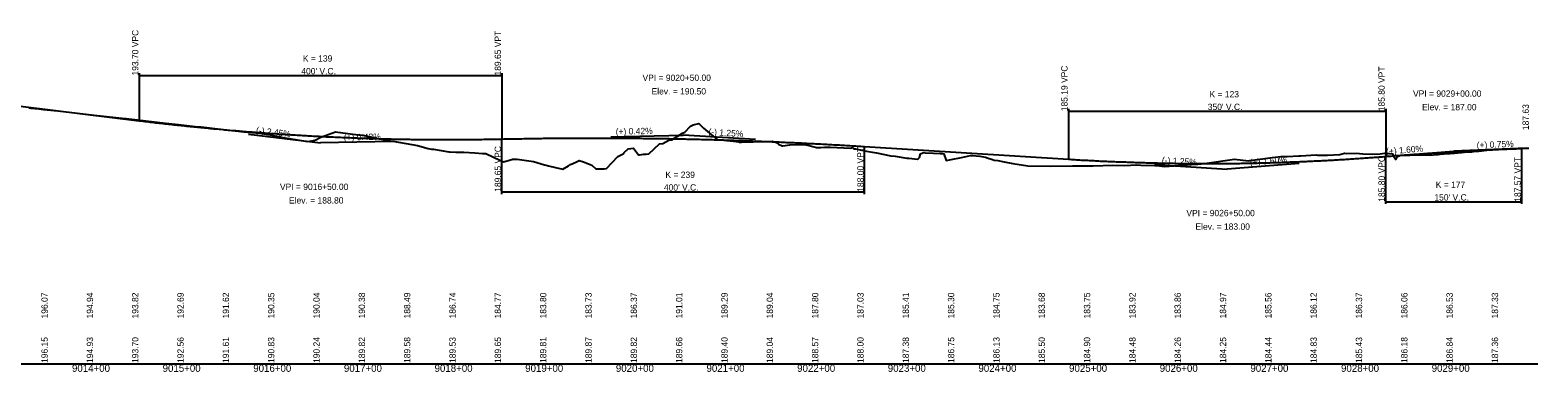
# Model space of a CAD drawing. Extents: x 1876258 to 1932803, y 754739 to 837911.
# Drawn here: x 1879018 to 1880682, y 765980 to 766358 of the extents above; entities that cross this region are included whole.
import ezdxf

# ---------------------------------------------------------------- set-up
doc = ezdxf.new("R2010")
doc.units = 0
for name, color, linetype in [('RD_DDB_GradeTX', 7, 'Continuous'), ('RD_DDB_Profile_EX', 7, 'Continuous'), ('RD_DDB_Profile_Lbl', 7, 'Continuous'), ('RD_DDB_Profile_PR', 7, 'Continuous'), ('RD_DDB_StaTX', 7, 'Continuous'), ('RD_DDB_StripGrade', 7, 'Continuous'), ('RD_DDB_VCLbl', 7, 'Continuous'), ('RD_GPK_Profile_Cell', 7, 'Continuous')]:
    doc.layers.add(name, color=color, linetype=linetype)

msp = doc.modelspace()

# ---------------------------------------------------------------- linework, layer by layer
at = {"layer": 'RD_DDB_GradeTX'}
for p, q in [((1879259.3, 766242.9), (1879338.8, 766233.1)), ((1879418.7, 766234.8), (1879338.8, 766233.1)), ((1879658.8, 766239.9), (1879738.8, 766241.6)), ((1879818.6, 766236.7), (1879738.8, 766241.6)), ((1880509, 766217.8), (1880588.8, 766224.1)), ((1880668.7, 766227.2), (1880588.8, 766224.1)), ((1880258.9, 766209.1), (1880338.8, 766204.1)), ((1880418.5, 766210.5), (1880338.8, 766204.1))]:
    msp.add_line(p, q, dxfattribs=at)
at = {"layer": 'RD_DDB_Profile_EX'}
for points in [[(1879016.8, 766271.9), (1879019.1, 766271.6), (1879027.9, 766270.7), (1879033, 766270.1), (1879049, 766268.4), (1879089.1, 766263.8), (1879123.3, 766260), (1879124.4, 766259.9), (1879167.7, 766254.9), (1879182, 766253.3), (1879182.1, 766253.3), (1879200.5, 766251.3), (1879207, 766250.7), (1879228.3, 766248.4), (1879254, 766245.5), (1879271.6, 766243.7), (1879283.3, 766242.1), (1879295.1, 766239.5), (1879324.4, 766234.8), (1879330.9, 766235.8), (1879331.3, 766235.8), (1879333.7, 766236.5), (1879339.1, 766239.5), (1879355.1, 766245.3), (1879374.2, 766242.8), (1879384.4, 766241.8), (1879385.7, 766241.7), (1879402.1, 766238.1), (1879415.4, 766235.5), (1879418.4, 766235.1), (1879439.4, 766231.5), (1879445.8, 766230.4), (1879457.6, 766227), (1879459.3, 766226.7), (1879461.1, 766226.1), (1879463.5, 766226.1), (1879480.4, 766223.2), (1879481.2, 766223.1), (1879487.9, 766222.8), (1879494.5, 766223), (1879496.9, 766222.7), (1879509, 766222.1), (1879517.4, 766221.5), (1879521.2, 766221.4), (1879537.2, 766213.8), (1879540.4, 766212.2), (1879549.8, 766214.9), (1879550.5, 766215.2), (1879550.5, 766215.3), (1879550.8, 766215.2), (1879551.1, 766215.1), (1879551.8, 766215.2), (1879555.7, 766215.3)], [(1879555.7, 766215.3), (1879558.2, 766214.9), (1879573.8, 766212.5), (1879585.9, 766208.7), (1879587.5, 766208.4), (1879590.1, 766207.9), (1879598, 766205.9), (1879606.1, 766204), (1879612.3, 766207.8), (1879614.6, 766209.4), (1879620.2, 766211.8), (1879624.2, 766213.7), (1879628.7, 766212.2), (1879638, 766208.4), (1879642.3, 766204.6), (1879644.1, 766204.5), (1879645.1, 766204.5), (1879646.9, 766204.4), (1879647.5, 766204.4), (1879648.2, 766204.5), (1879651.7, 766204.3), (1879654, 766204.8), (1879666.6, 766218.1), (1879672.7, 766220.9), (1879673.7, 766222.4), (1879678.1, 766226.7), (1879683.9, 766227.3), (1879689.6, 766219.8), (1879690.5, 766219.8), (1879693.1, 766220.4), (1879695, 766220.6), (1879697.8, 766220.8), (1879701, 766221.1), (1879712.6, 766232.2), (1879716.2, 766232.3), (1879722.8, 766236.3), (1879722.8, 766236.3), (1879726.2, 766236.5), (1879738.1, 766243.9), (1879740.5, 766244.9), (1879746.8, 766251.6), (1879749.7, 766253), (1879755.9, 766254.7), (1879761.2, 766249.4), (1879776.2, 766236.8), (1879794.1, 766235.1), (1879800.1, 766234.2), (1879800.8, 766234.1), (1879801.2, 766234.1), (1879801.5, 766234), (1879803.1, 766234.1), (1879828.7, 766234.7), (1879836.9, 766234.9), (1879841.6, 766233.5), (1879844.1, 766231.6), (1879848.1, 766229.7), (1879848.8, 766229.8), (1879856.4, 766230.9), (1879864.2, 766231.2), (1879872.9, 766231.3), (1879873.8, 766231.3), (1879874.2, 766231.1), (1879874.9, 766230.9), (1879883.4, 766228.6), (1879885.8, 766228), (1879887.5, 766228), (1879890.5, 766228.2), (1879894.5, 766228.5), (1879899.1, 766228.4), (1879901, 766228.4), (1879923.8, 766227.3), (1879925.3, 766227.9), (1879926.6, 766227.1), (1879927.8, 766226.5), (1879928.8, 766226.7), (1879941.1, 766223.8), (1879952, 766222.2), (1879967.8, 766218.8), (1879972.5, 766218.3), (1879985.4, 766216.1), (1879987.7, 766216.3), (1879997.2, 766215.2), (1879997.9, 766215.4), (1879999.4, 766217), (1880000.6, 766221.2), (1880003.2, 766222.3), (1880003.7, 766222.5), (1880005.9, 766222.3), (1880014.9, 766221.6), (1880022.1, 766221.4), (1880024.4, 766221.3), (1880026.4, 766221), (1880028.9, 766213.8), (1880034.4, 766214.7), (1880045.7, 766217.1), (1880055.6, 766219.3), (1880057.4, 766219.2), (1880057.7, 766219.2), (1880058.1, 766219.1), (1880066, 766218.5), (1880072.3, 766217.4)], [(1880072.3, 766217.4), (1880075.3, 766216.2), (1880080.1, 766214.9), (1880082, 766214), (1880085.9, 766213.6), (1880092.9, 766212), (1880102.5, 766210.2), (1880119.1, 766207.8), (1880143.6, 766207.5), (1880168.3, 766207.6), (1880170.2, 766207.7), (1880190.9, 766207.9), (1880212.9, 766208.4), (1880225.6, 766208.3), (1880239.4, 766208.8), (1880243.6, 766208.4), (1880259, 766208.2), (1880264.3, 766207.8), (1880269.5, 766207.2), (1880280.4, 766207.8), (1880299.7, 766209.3), (1880306.5, 766209.5), (1880310.3, 766209.8), (1880313.8, 766210.4), (1880346.8, 766215.1), (1880362.4, 766213.4), (1880364, 766213.8), (1880388.9, 766217), (1880398.1, 766218), (1880405.2, 766218.2), (1880418.1, 766218.7), (1880419, 766218.7), (1880419.8, 766218.7), (1880436.9, 766219.8), (1880438.5, 766219.7), (1880449.7, 766219.5), (1880463, 766220.4), (1880468.4, 766221.6), (1880470.1, 766221.5), (1880481.1, 766221.8), (1880488.4, 766221), (1880499.2, 766220.8), (1880507.6, 766220.9), (1880513, 766221.7), (1880517.9, 766221.5), (1880521.1, 766221.1), (1880522.4, 766218.3), (1880524.9, 766214.8), (1880526.8, 766218), (1880530.4, 766219.6), (1880540.5, 766219.4), (1880552.3, 766220), (1880552.4, 766220), (1880552.5, 766220), (1880563.5, 766219.7), (1880568.7, 766220.2), (1880570.6, 766220.3), (1880571.8, 766220.4), (1880576.2, 766220.9), (1880577.6, 766221), (1880578.2, 766221), (1880584.9, 766221.5), (1880589.7, 766221.9), (1880593.2, 766222.2), (1880597.4, 766222.4), (1880600.8, 766222.7), (1880605.7, 766223.2), (1880608.7, 766223.4), (1880612.5, 766223.8), (1880615.1, 766224), (1880616.6, 766224), (1880625.3, 766225.1), (1880657.4, 766226.8), (1880658.8, 766226.9), (1880658.9, 766226.9), (1880658.9, 766226.9), (1880659.4, 766226.8), (1880664.7, 766227), (1880669.2, 766227.2), (1880669.7, 766227.2), (1880671.7, 766227.3)]]:
    msp.add_lwpolyline(points, dxfattribs=at)
at = {"layer": 'RD_DDB_Profile_PR'}
for p, q in [((1878978.8, 766277.2), (1879138.8, 766257.6)), ((1879938.8, 766229.1), (1880163.8, 766215.1)), ((1880663.8, 766227), (1880671.7, 766227.3))]:
    msp.add_line(p, q, dxfattribs=at)
for points in [[(1879138.8, 766257.6), (1879146.8, 766256.7), (1879154.8, 766255.7), (1879162.8, 766254.8), (1879170.8, 766253.9), (1879178.8, 766253), (1879186.8, 766252.2), (1879194.8, 766251.3), (1879202.8, 766250.5), (1879210.8, 766249.8), (1879218.8, 766249), (1879226.8, 766248.3), (1879234.8, 766247.5), (1879242.8, 766246.8), (1879250.8, 766246.2), (1879258.8, 766245.5), (1879266.8, 766244.9), (1879274.8, 766244.3), (1879282.8, 766243.7), (1879290.8, 766243.2), (1879298.8, 766242.6), (1879306.8, 766242.1), (1879314.8, 766241.6), (1879322.8, 766241.2), (1879330.8, 766240.7), (1879338.8, 766240.3), (1879346.8, 766239.9), (1879354.8, 766239.6), (1879362.8, 766239.2), (1879370.8, 766238.9), (1879378.8, 766238.6), (1879386.8, 766238.3), (1879394.8, 766238.1), (1879402.8, 766237.8), (1879410.8, 766237.6), (1879418.8, 766237.4), (1879426.8, 766237.3), (1879434.8, 766237.1), (1879442.8, 766237), (1879450.8, 766236.9), (1879458.8, 766236.8), (1879466.8, 766236.8), (1879474.8, 766236.8), (1879482.8, 766236.8), (1879490.8, 766236.8), (1879498.8, 766236.8), (1879506.8, 766236.9), (1879514.8, 766237), (1879522.8, 766237.1), (1879530.8, 766237.2), (1879538.8, 766237.4)], [(1879538.8, 766237.4), (1879546.8, 766237.6), (1879554.8, 766237.7), (1879562.8, 766237.8), (1879570.8, 766238), (1879578.8, 766238.1), (1879586.8, 766238.2), (1879594.8, 766238.3), (1879602.8, 766238.3), (1879610.8, 766238.4), (1879618.8, 766238.4), (1879626.8, 766238.5), (1879634.8, 766238.5), (1879642.8, 766238.5), (1879650.8, 766238.5), (1879658.8, 766238.4), (1879666.8, 766238.4), (1879674.8, 766238.3), (1879682.8, 766238.3), (1879690.8, 766238.2), (1879698.8, 766238.1), (1879706.8, 766238), (1879714.8, 766237.9), (1879722.8, 766237.8), (1879730.8, 766237.6), (1879738.8, 766237.5), (1879746.8, 766237.3), (1879754.8, 766237.1), (1879762.8, 766236.9), (1879770.8, 766236.7), (1879778.8, 766236.5), (1879786.8, 766236.2), (1879794.8, 766236), (1879802.8, 766235.7), (1879810.8, 766235.4), (1879818.8, 766235.1), (1879826.8, 766234.8), (1879834.8, 766234.5), (1879842.8, 766234.2), (1879850.8, 766233.8), (1879858.8, 766233.5), (1879866.8, 766233.1), (1879874.8, 766232.7), (1879882.8, 766232.3), (1879890.8, 766231.9), (1879898.8, 766231.5), (1879906.8, 766231), (1879914.8, 766230.6), (1879922.8, 766230.1), (1879930.8, 766229.6), (1879938.8, 766229.1)], [(1880163.8, 766215.1), (1880170.8, 766214.7), (1880177.8, 766214.2), (1880184.8, 766213.9), (1880191.8, 766213.5), (1880198.8, 766213.1), (1880205.8, 766212.8), (1880212.8, 766212.5), (1880219.8, 766212.2), (1880226.8, 766212), (1880233.8, 766211.7), (1880240.8, 766211.5), (1880247.8, 766211.3), (1880254.8, 766211.1), (1880261.8, 766210.9), (1880268.8, 766210.8), (1880275.8, 766210.6), (1880282.8, 766210.5), (1880289.8, 766210.4), (1880296.8, 766210.4), (1880303.8, 766210.3), (1880310.8, 766210.3), (1880317.8, 766210.3), (1880324.8, 766210.3), (1880331.8, 766210.3), (1880338.8, 766210.4), (1880345.8, 766210.4), (1880352.8, 766210.5), (1880359.8, 766210.7), (1880366.8, 766210.8), (1880373.8, 766210.9), (1880380.8, 766211.1), (1880387.8, 766211.3), (1880394.8, 766211.5), (1880401.8, 766211.7), (1880408.8, 766212), (1880415.8, 766212.3), (1880422.8, 766212.5), (1880429.8, 766212.9), (1880436.8, 766213.2), (1880443.8, 766213.5), (1880450.8, 766213.9), (1880457.8, 766214.3), (1880464.8, 766214.7), (1880471.8, 766215.1), (1880478.8, 766215.6), (1880485.8, 766216.1), (1880492.8, 766216.6), (1880499.8, 766217.1), (1880506.8, 766217.6), (1880513.8, 766218.1)], [(1880513.8, 766218.1), (1880516.8, 766218.4), (1880519.8, 766218.6), (1880522.8, 766218.9), (1880525.8, 766219.1), (1880528.8, 766219.3), (1880531.8, 766219.5), (1880534.8, 766219.8), (1880537.8, 766220), (1880540.8, 766220.2), (1880543.8, 766220.4), (1880546.8, 766220.6), (1880549.8, 766220.8), (1880552.8, 766221), (1880555.8, 766221.3), (1880558.8, 766221.5), (1880561.8, 766221.7), (1880564.8, 766221.9), (1880567.8, 766222.1), (1880570.8, 766222.2), (1880573.8, 766222.4), (1880576.8, 766222.6), (1880579.8, 766222.8), (1880582.8, 766223), (1880585.8, 766223.2), (1880588.8, 766223.3), (1880591.8, 766223.5), (1880594.8, 766223.7), (1880597.8, 766223.9), (1880600.8, 766224), (1880603.8, 766224.2), (1880606.8, 766224.4), (1880609.8, 766224.5), (1880612.8, 766224.7), (1880615.8, 766224.8), (1880618.8, 766225), (1880621.8, 766225.1), (1880624.8, 766225.3), (1880627.8, 766225.4), (1880630.8, 766225.6), (1880633.8, 766225.7), (1880636.8, 766225.8), (1880639.8, 766226), (1880642.8, 766226.1), (1880645.8, 766226.2), (1880648.8, 766226.4), (1880651.8, 766226.5), (1880654.8, 766226.6), (1880657.8, 766226.7), (1880660.8, 766226.9), (1880663.8, 766227)]]:
    msp.add_spline(points, degree=3, dxfattribs=at)
at = {"layer": 'RD_DDB_VCLbl'}
for p, q in [((1879138.8, 766310.1), (1879138.8, 766257.6)), ((1879138.8, 766307.6), (1879538.8, 766307.6)), ((1879538.8, 766310.1), (1879538.8, 766237.4)), ((1880163.8, 766270.6), (1880163.8, 766215.1)), ((1880163.8, 766268.1), (1880513.8, 766268.1)), ((1880513.8, 766270.6), (1880513.8, 766218.1)), ((1879538.8, 766176.6), (1879538.8, 766237.4)), ((1879938.8, 766176.6), (1879938.8, 766229.1)), ((1880513.8, 766165.6), (1880513.8, 766218.1)), ((1880663.8, 766165.6), (1880663.8, 766227)), ((1879538.8, 766179.1), (1879938.8, 766179.1)), ((1880513.8, 766168.1), (1880663.8, 766168.1))]:
    msp.add_line(p, q, dxfattribs=at)
at = {"layer": 'RD_GPK_Profile_Cell'}
msp.add_line((1877681.6, 765989.1), (1880681.6, 765989.1), dxfattribs=at)

# ---------------------------------------------------------------- texts
at = {"layer": 'RD_DDB_GradeTX'}
for s, rotation, p in [('(-) 2.45%', 353.0161, (1879267.2, 766243.9)), ('(+) 0.42%', 1.2174, (1879664.4, 766242.1)), ('(-) 1.25%', 356.4237, (1879766.5, 766241.9)), ('(+) 0.42%', 1.2174, (1879364.4, 766235.7)), ('(+) 0.75%', 2.1577, (1880614.3, 766227.1)), ('(-) 1.25%', 356.4237, (1880266.7, 766210.7)), ('(+) 1.60%', 4.5739, (1880364.2, 766208.2)), ('(+) 1.60%', 4.5739, (1880514.5, 766220.2))]:
    msp.add_text(s, height=7, rotation=rotation, dxfattribs=at).set_placement(p)
at = {"layer": 'RD_DDB_Profile_Lbl'}
for s, p in [('VPI = 9020+50.00', (1879693.9, 766301.6)), ('Elev. = 190.50', (1879703.9, 766286.6)), ('VPI = 9029+00.00', (1880543.9, 766284.1)), ('Elev. = 187.00', (1880553.9, 766269.1)), ('VPI = 9016+50.00', (1879293.9, 766181.1)), ('Elev. = 188.80', (1879303.9, 766166.1)), ('VPI = 9026+50.00', (1880293.9, 766152.1)), ('Elev. = 183.00', (1880303.9, 766137.1))]:
    msp.add_text(s, height=7, dxfattribs=at).set_placement(p)
msp.add_text('187.63', height=7, rotation=90, dxfattribs=at).set_placement((1880671.7, 766247.3))
at = {"layer": 'RD_DDB_StaTX'}
for s, p in [('9014+00', (1879064.5, 765980.1)), ('9015+00', (1879164.5, 765980.1)), ('9016+00', (1879264.5, 765980.1)), ('9017+00', (1879364.5, 765980.1)), ('9018+00', (1879464.5, 765980.1)), ('9019+00', (1879564.5, 765980.1)), ('9020+00', (1879664.5, 765980.1)), ('9021+00', (1879764.5, 765980.1)), ('9022+00', (1879864.5, 765980.1)), ('9023+00', (1879964.5, 765980.1)), ('9024+00', (1880064.5, 765980.1)), ('9025+00', (1880164.5, 765980.1)), ('9026+00', (1880264.5, 765980.1)), ('9027+00', (1880364.5, 765980.1)), ('9028+00', (1880464.5, 765980.1)), ('9029+00', (1880564.5, 765980.1))]:
    msp.add_text(s, height=8, dxfattribs=at).set_placement(p)
at = {"layer": 'RD_DDB_StripGrade'}
for s, p in [('193.70 VPC', (1879137.8, 766307.6)), ('189.65 VPT', (1879537.8, 766307.6)), ('185.19 VPC', (1880162.8, 766268.1)), ('185.80 VPT', (1880512.8, 766268.1)), ('189.65 VPC', (1879537.8, 766179.1)), ('188.00 VPT', (1879937.8, 766179.1)), ('185.80 VPC', (1880512.8, 766168.1)), ('187.57 VPT', (1880662.8, 766168.1)), ('196.07', (1879037.8, 766039.1)), ('194.94', (1879087.8, 766039.1)), ('193.82', (1879137.8, 766039.1)), ('192.69', (1879187.8, 766039.1)), ('191.62', (1879237.8, 766039.1)), ('190.35', (1879287.8, 766039.1)), ('190.04', (1879337.8, 766039.1)), ('190.38', (1879387.8, 766039.1)), ('188.49', (1879437.8, 766039.1)), ('186.74', (1879487.8, 766039.1)), ('184.77', (1879537.8, 766039.1)), ('183.80', (1879587.8, 766039.1)), ('183.73', (1879637.8, 766039.1)), ('186.37', (1879687.8, 766039.1)), ('191.01', (1879737.8, 766039.1)), ('189.29', (1879787.8, 766039.1)), ('189.04', (1879837.8, 766039.1)), ('187.80', (1879887.8, 766039.1)), ('187.03', (1879937.8, 766039.1)), ('185.41', (1879987.8, 766039.1)), ('185.30', (1880037.8, 766039.1)), ('184.75', (1880087.8, 766039.1)), ('183.68', (1880137.8, 766039.1)), ('183.75', (1880187.8, 766039.1)), ('183.92', (1880237.8, 766039.1)), ('183.86', (1880287.8, 766039.1)), ('184.97', (1880337.8, 766039.1)), ('185.56', (1880387.8, 766039.1)), ('186.12', (1880437.8, 766039.1)), ('186.37', (1880487.8, 766039.1)), ('186.06', (1880537.8, 766039.1)), ('186.53', (1880587.8, 766039.1)), ('187.33', (1880637.8, 766039.1)), ('196.15', (1879037.8, 765989.9)), ('194.93', (1879087.8, 765989.9)), ('193.70', (1879137.8, 765989.9)), ('192.56', (1879187.8, 765989.9)), ('191.61', (1879237.8, 765989.9)), ('190.83', (1879287.8, 765989.9)), ('190.24', (1879337.8, 765989.9)), ('189.82', (1879387.8, 765989.9)), ('189.58', (1879437.8, 765989.9)), ('189.53', (1879487.8, 765989.9)), ('189.65', (1879537.8, 765989.9)), ('189.81', (1879587.8, 765989.9)), ('189.87', (1879637.8, 765989.9)), ('189.82', (1879687.8, 765989.9)), ('189.66', (1879737.8, 765989.9)), ('189.40', (1879787.8, 765989.9)), ('189.04', (1879837.8, 765989.9)), ('188.57', (1879887.8, 765989.9)), ('188.00', (1879937.8, 765989.9)), ('187.38', (1879987.8, 765989.9)), ('186.75', (1880037.8, 765989.9)), ('186.13', (1880087.8, 765989.9)), ('185.50', (1880137.8, 765989.9)), ('184.90', (1880187.8, 765989.9)), ('184.48', (1880237.8, 765989.9)), ('184.26', (1880287.8, 765989.9)), ('184.25', (1880337.8, 765989.9)), ('184.44', (1880387.8, 765989.9)), ('184.83', (1880437.8, 765989.9)), ('185.43', (1880487.8, 765989.9)), ('186.18', (1880537.8, 765989.9)), ('186.84', (1880587.8, 765989.9)), ('187.36', (1880637.8, 765989.9))]:
    msp.add_text(s, height=7, rotation=90, dxfattribs=at).set_placement(p)
at = {"layer": 'RD_DDB_VCLbl'}
for s, p in [("400' V.C.", (1879317.5, 766308.9)), ('K = 139', (1879319.2, 766322.9)), ('K = 123', (1880319.4, 766283.4)), ("350' V.C.", (1880317.5, 766269.4)), ('K = 239', (1879719.2, 766194.4)), ("400' V.C.", (1879717.5, 766180.4)), ('K = 177', (1880569, 766183.4)), ("150' V.C.", (1880567.5, 766169.4))]:
    msp.add_text(s, height=7, dxfattribs=at).set_placement(p)

doc.saveas('drawing.dxf')
